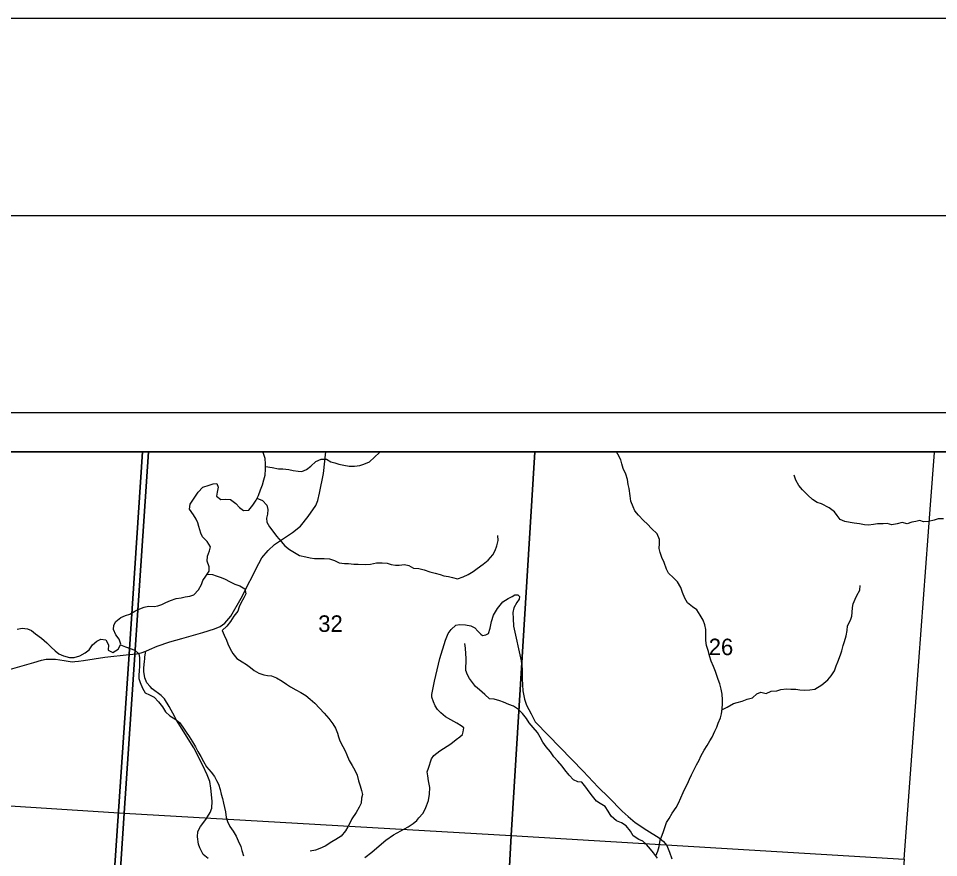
# Model space of a CAD drawing. Extents: x 0 to 34, y 0 to 22.
# Drawn here: x 5.215 to 7.55, y 19.87 to 22 of the extents above; entities that cross this region are included whole.
import ezdxf

# ---------------------------------------------------------------- set-up
doc = ezdxf.new("R2010")
doc.units = 0
for name, color, linetype in [('Default', 7, 'Continuous'), ('GM_X_County_Road', 7, 'Continuous'), ('GM_X_Major_River', 7, 'Continuous'), ('GM_X_Minor_River', 7, 'Continuous'), ('GM_X_Section', 7, 'Continuous'), ('GM_X_Section_Text', 7, 'Continuous'), ('GM_X_State_Route', 7, 'Continuous'), ('GM_X_Township_Road', 7, 'Continuous'), ('SC_Scratch1', 7, 'Continuous'), ('SH_Border', 7, 'Continuous'), ('SH_Cut_Line', 7, 'Continuous'), ('SH_Data', 7, 'Continuous')]:
    doc.layers.add(name, color=color, linetype=linetype)

msp = doc.modelspace()

# ---------------------------------------------------------------- linework, layer by layer
at = {"layer": 'Default'}
for points in [[(5.5445, 20.9), (4.5292, 20.9), (4.4687, 20.0485), (5.483, 19.983)], [(6.5255, 20.9), (5.5445, 20.9), (5.483, 19.983), (6.465, 19.9265)], [(7.5178, 20.9), (6.5255, 20.9), (6.465, 19.9265), (7.462, 19.8663), (7.4997, 20.3683), (7.5295, 20.7659), (7.5396, 20.8985)]]:
    msp.add_lwpolyline(points, close=True, dxfattribs=at)
at = {"layer": 'GM_X_County_Road'}
msp.add_lwpolyline([(5.6967, 19.8686), (5.6838, 19.8781), (5.675, 19.8949), (5.672, 19.9048), (5.6695, 19.9234), (5.6704, 19.9371), (5.6769, 19.9496), (5.6904, 19.9675), (5.7013, 19.9847), (5.7055, 19.9956), (5.7065, 20.0133), (5.7034, 20.0463), (5.7003, 20.0635), (5.6939, 20.0806), (5.6826, 20.1041), (5.66, 20.1491), (5.6159, 20.2195), (5.6119, 20.228), (5.5973, 20.254), (5.5853, 20.2733), (5.5768, 20.2816), (5.5544, 20.2984), (5.5489, 20.3048), (5.541, 20.314), (5.5358, 20.3265), (5.5327, 20.3424), (5.5332, 20.3518), (5.5346, 20.3681), (5.5352, 20.3748), (5.536, 20.3803), (5.5385, 20.3944)], dxfattribs=at)
at = {"layer": 'GM_X_Major_River'}
for points in [[(5.3175, 20.3879), (5.3296, 20.3821), (5.3443, 20.3786), (5.3561, 20.3781), (5.3705, 20.3822), (5.3846, 20.39), (5.3942, 20.3976), (5.403, 20.4104), (5.414, 20.4198), (5.4243, 20.4246), (5.4368, 20.4227), (5.4436, 20.4101), (5.4427, 20.3972), (5.454, 20.391), (5.4678, 20.3993), (5.475, 20.4125), (5.4706, 20.4251), (5.4623, 20.4361), (5.456, 20.4494), (5.4572, 20.4601), (5.4622, 20.4699), (5.4744, 20.48), (5.4869, 20.4849), (5.4979, 20.4886), (5.5105, 20.4957), (5.5231, 20.5017), (5.5341, 20.5062), (5.5451, 20.5083), (5.5591, 20.5079), (5.569, 20.5097), (5.5785, 20.5126), (5.5892, 20.5175), (5.6006, 20.5227), (5.6154, 20.5279), (5.6276, 20.5297), (5.6382, 20.5319), (5.65, 20.5341), (5.6602, 20.5375), (5.6721, 20.5499), (5.679, 20.5631), (5.6828, 20.5733), (5.6905, 20.5847), (5.6989, 20.5975), (5.6986, 20.6081), (5.6934, 20.6226), (5.695, 20.6355), (5.7, 20.6487), (5.702, 20.6593), (5.6941, 20.6726), (5.6821, 20.6841), (5.6776, 20.694), (5.6728, 20.7103), (5.6705, 20.7198), (5.6661, 20.7297), (5.6589, 20.7404), (5.6492, 20.7549), (5.6504, 20.7674), (5.6592, 20.7802), (5.6707, 20.798), (5.6829, 20.8104), (5.6985, 20.8156), (5.7088, 20.8193), (5.7186, 20.8196), (5.722, 20.8101), (5.7188, 20.7976), (5.7176, 20.7878), (5.7286, 20.779), (5.7404, 20.78), (5.7532, 20.7792), (5.7665, 20.7692), (5.7759, 20.7585), (5.7861, 20.7509), (5.7997, 20.7523), (5.8097, 20.7651), (5.8177, 20.7776), (5.8239, 20.7897), (5.8289, 20.8033), (5.8339, 20.8165), (5.8378, 20.8294), (5.8409, 20.8411), (5.8421, 20.8559), (5.8418, 20.8699), (5.8408, 20.8836), (5.8363, 20.8981), (5.8356, 20.9)], [(5.2117, 20.4505), (5.2242, 20.4531), (5.2375, 20.4514), (5.2477, 20.4468), (5.2583, 20.438), (5.2734, 20.4269), (5.2869, 20.4158), (5.2982, 20.4047), (5.3077, 20.3948), (5.3175, 20.3879)]]:
    msp.add_lwpolyline(points, dxfattribs=at)
at = {"layer": 'GM_X_Minor_River'}
for points in [[(5.842, 20.8628), (5.8583, 20.8603), (5.8749, 20.8573), (5.8855, 20.8573), (5.9007, 20.8555), (5.9117, 20.8529), (5.9245, 20.851), (5.9344, 20.8503), (5.9461, 20.8556), (5.9571, 20.8636), (5.9691, 20.8757), (5.9827, 20.8818), (5.9964, 20.8819), (6.0074, 20.8747), (6.018, 20.8724), (6.0282, 20.8691), (6.0403, 20.8664), (6.0543, 20.8638), (6.068, 20.8635), (6.0812, 20.8654), (6.091, 20.8685), (6.1054, 20.8746), (6.1182, 20.8867), (6.1307, 20.8981), (6.132, 20.9)], [(6.8319, 19.8746), (6.8376, 19.8865), (6.8406, 19.899), (6.8432, 19.9146), (6.8485, 19.9271), (6.8519, 19.9366), (6.8552, 19.9472), (6.859, 19.9593), (6.8658, 19.97), (6.874, 19.9836), (6.8842, 19.9973), (6.8895, 20.0083), (6.8955, 20.0224), (6.9019, 20.0356), (6.9068, 20.0463), (6.9124, 20.0573), (6.9173, 20.0698), (6.9226, 20.0808), (6.9286, 20.0922), (6.9354, 20.1059), (6.9418, 20.1176), (6.9466, 20.1275), (6.9553, 20.143), (6.9621, 20.1552), (6.9692, 20.1666), (6.9753, 20.1765), (6.982, 20.1909), (6.9873, 20.2015), (6.9903, 20.2114), (6.9963, 20.2254), (6.9989, 20.2349), (7.0004, 20.2478), (7.0015, 20.2611), (7.0018, 20.2709), (7.0003, 20.2849), (6.9983, 20.2978), (6.9945, 20.3118), (6.9903, 20.3224), (6.9869, 20.3327), (6.9838, 20.3429), (6.9785, 20.355), (6.9724, 20.369), (6.9685, 20.3823), (6.9655, 20.3933), (6.9609, 20.4084), (6.9593, 20.4217), (6.9592, 20.4497), (6.9562, 20.4615), (6.952, 20.4728), (6.9444, 20.4857), (6.936, 20.499), (6.9257, 20.5069), (6.9128, 20.5167), (6.9056, 20.5292), (6.9003, 20.5429), (6.8961, 20.5557), (6.8869, 20.5701), (6.8767, 20.58), (6.8645, 20.5921), (6.8596, 20.6023), (6.8531, 20.6189), (6.8477, 20.6322), (6.8435, 20.6447), (6.8405, 20.6549), (6.8412, 20.6674), (6.8412, 20.6781), (6.8354, 20.6917), (6.8214, 20.7057), (6.8115, 20.717), (6.8013, 20.7257), (6.7887, 20.7394), (6.7788, 20.7507), (6.7747, 20.7605), (6.7689, 20.7753), (6.7674, 20.7886), (6.7643, 20.8075), (6.762, 20.8174), (6.76, 20.8299), (6.7562, 20.8435), (6.7497, 20.8579), (6.7459, 20.8697), (6.7432, 20.8795), (6.736, 20.8943), (6.7326, 20.9)], [(7.2528, 20.7678), (7.2414, 20.7712), (7.2296, 20.7795), (7.2178, 20.7904), (7.2045, 20.8037), (7.195, 20.815), (7.1878, 20.8279), (7.1836, 20.8408)], [(5.8201, 20.7823), (5.8343, 20.7768), (5.8453, 20.7644), (5.848, 20.7537), (5.8473, 20.7416), (5.8447, 20.7317), (5.8455, 20.7219), (5.8519, 20.7098), (5.8607, 20.6992), (5.8698, 20.6859), (5.8812, 20.6723), (5.8907, 20.6617), (5.9025, 20.6523), (5.9154, 20.6447), (5.9279, 20.6375), (5.9445, 20.6334), (5.9548, 20.6312), (5.9658, 20.6297), (5.9782, 20.6297), (5.9907, 20.6294), (6.0044, 20.6283), (6.0165, 20.6241), (6.0286, 20.6188), (6.0419, 20.617), (6.0521, 20.617), (6.0661, 20.6148), (6.0771, 20.6148), (6.0949, 20.6144), (6.1085, 20.6152), (6.1233, 20.6183), (6.1376, 20.6183), (6.1509, 20.6176), (6.1604, 20.6146), (6.1714, 20.6127), (6.1812, 20.6128), (6.1941, 20.6139), (6.2051, 20.6117), (6.2176, 20.6053), (6.2312, 20.6038), (6.2445, 20.6008), (6.2585, 20.5955), (6.2721, 20.5925), (6.2846, 20.5887), (6.2941, 20.5857), (6.3058, 20.5835), (6.3164, 20.5809), (6.3286, 20.5782), (6.3433, 20.5828), (6.3558, 20.5889), (6.369, 20.5965), (6.3792, 20.6038), (6.3943, 20.6152), (6.4071, 20.6251), (6.4185, 20.6391), (6.4249, 20.6497), (6.4286, 20.6619), (6.4323, 20.6752), (6.4316, 20.6877)], [(7.5624, 20.7305), (7.5488, 20.7302), (7.5389, 20.7271), (7.5245, 20.7237), (7.5113, 20.7229), (7.5018, 20.726), (7.4916, 20.7237), (7.4818, 20.7218), (7.4696, 20.7176), (7.4571, 20.721), (7.4443, 20.7176), (7.4314, 20.7149), (7.4189, 20.718), (7.4087, 20.7176), (7.3951, 20.7176), (7.3848, 20.7157), (7.3716, 20.7141), (7.3617, 20.7145), (7.3492, 20.7175), (7.3356, 20.7194), (7.325, 20.7206), (7.3117, 20.7236), (7.2996, 20.7281), (7.292, 20.7384), (7.2852, 20.7482), (7.2719, 20.7577), (7.2528, 20.7678)], [(5.6939, 20.5898), (5.707, 20.5889), (5.7168, 20.5859), (5.7289, 20.581), (5.7392, 20.5768), (5.7502, 20.5712), (5.7638, 20.5647), (5.7767, 20.5602), (5.7892, 20.5523), (5.7919, 20.5394), (5.787, 20.5299), (5.7795, 20.5162), (5.7754, 20.5064), (5.7712, 20.4958), (5.7614, 20.4828), (5.7528, 20.4696), (5.7433, 20.4578), (5.732, 20.4464), (5.7366, 20.4346), (5.7431, 20.4225), (5.7465, 20.4127), (5.7519, 20.4006), (5.7591, 20.3884), (5.769, 20.3756), (5.783, 20.3669), (5.7932, 20.3605), (5.8035, 20.3529), (5.813, 20.3454), (5.8251, 20.3389), (5.8372, 20.3344), (5.8467, 20.3325), (5.8569, 20.3314), (5.8694, 20.3265), (5.8842, 20.3179), (5.8949, 20.3107), (5.9055, 20.3039), (5.9184, 20.2963), (5.9313, 20.2895), (5.9442, 20.282), (5.9555, 20.2729), (5.9673, 20.2623), (5.9909, 20.2366), (6.0026, 20.2234), (6.0129, 20.2097), (6.0194, 20.1988), (6.0243, 20.1863), (6.027, 20.1768), (6.0308, 20.1666), (6.0381, 20.1526), (6.0438, 20.1412), (6.048, 20.131), (6.0545, 20.1173), (6.0613, 20.1041), (6.0689, 20.0927), (6.0746, 20.0795), (6.0781, 20.0655), (6.0823, 20.053), (6.0854, 20.0409), (6.0877, 20.0306), (6.0858, 20.0211), (6.0843, 20.0082), (6.0791, 19.9988), (6.0719, 19.9851), (6.061, 19.9691), (6.0557, 19.9581), (6.0508, 19.9487), (6.0444, 19.938), (6.0339, 19.9247), (6.0199, 19.9167), (6.0097, 19.9103), (5.9935, 19.8996), (5.9798, 19.8935), (5.9685, 19.8897), (5.9553, 19.887)], [(7.2535, 20.309), (7.2683, 20.3216), (7.277, 20.3314), (7.2853, 20.3447), (7.2902, 20.3569), (7.2943, 20.3675), (7.3011, 20.3853), (7.3042, 20.3955), (7.3072, 20.4084), (7.3113, 20.4187), (7.3155, 20.4331), (7.3174, 20.4464), (7.3185, 20.4589), (7.3264, 20.4729), (7.3294, 20.4828), (7.3302, 20.4923), (7.3313, 20.5048), (7.3332, 20.5143), (7.3381, 20.5264), (7.3422, 20.5359), (7.3502, 20.5488), (7.3509, 20.5613)], [(5.4739, 20.4103), (5.4865, 20.4052), (5.4982, 20.4011), (5.5104, 20.3969), (5.5206, 20.3875), (5.5222, 20.378), (5.5222, 20.3685), (5.5218, 20.3572), (5.5215, 20.3435), (5.5208, 20.334), (5.5208, 20.3246), (5.5239, 20.3151), (5.5296, 20.3007), (5.5364, 20.2882), (5.5474, 20.2833), (5.5596, 20.2773), (5.5706, 20.2659), (5.5805, 20.2534), (5.5877, 20.2402), (5.5991, 20.2303), (5.6116, 20.2224), (5.6234, 20.2133), (5.6317, 20.2016), (5.6405, 20.1891), (5.6485, 20.1774), (5.6565, 20.1641), (5.6645, 20.1517), (5.6705, 20.1399), (5.6774, 20.1267), (5.6843, 20.1142), (5.6923, 20.1005), (5.704, 20.0869), (5.712, 20.0763), (5.7173, 20.0665), (5.7223, 20.0566), (5.7269, 20.0434), (5.7292, 20.0316), (5.7323, 20.0207), (5.7349, 20.0085), (5.7376, 19.9972), (5.7399, 19.9862), (5.7419, 19.9722), (5.7453, 19.9619), (5.751, 19.9491), (5.7598, 19.9373), (5.7674, 19.9252), (5.7723, 19.9127), (5.7788, 19.8987), (5.7819, 19.8889), (5.7857, 19.8748)], [(6.3504, 20.3872), (6.3496, 20.402), (6.3476, 20.4134)], [(6.8362, 19.8687), (6.8263, 19.8823), (6.8191, 19.8922), (6.8088, 19.9039), (6.7993, 19.9122), (6.7891, 19.9163), (6.7747, 19.9258), (6.7678, 19.9379), (6.7572, 19.9511), (6.745, 19.9591), (6.7325, 19.9636), (6.7193, 19.9753), (6.7109, 19.9882), (6.7033, 20.0003), (6.6908, 20.0078), (6.6813, 20.0139), (6.6714, 20.0267), (6.663, 20.0377), (6.655, 20.0494), (6.6444, 20.0615), (6.6346, 20.063), (6.6236, 20.0676), (6.6125, 20.08), (6.6015, 20.0929), (6.5947, 20.1027), (6.5833, 20.1156), (6.5738, 20.1258), (6.565, 20.1387), (6.5544, 20.1515), (6.5453, 20.1633), (6.5388, 20.1765), (6.5316, 20.1883), (6.5206, 20.2004), (6.5107, 20.2125), (6.5042, 20.2238), (6.4943, 20.2363), (6.4841, 20.2465), (6.4708, 20.2545), (6.459, 20.2594), (6.4458, 20.265), (6.4363, 20.2684), (6.4219, 20.2722), (6.4098, 20.2736), (6.398, 20.2842), (6.3844, 20.2963), (6.3745, 20.305), (6.3673, 20.3149), (6.3593, 20.3247), (6.3547, 20.3345), (6.3505, 20.3451), (6.3501, 20.355), (6.3512, 20.3649), (6.3512, 20.3762), (6.3504, 20.3872)], [(7.0001, 20.2455), (7.0136, 20.252), (7.0291, 20.2615), (7.039, 20.2638), (7.0514, 20.2672), (7.0639, 20.2722), (7.0775, 20.276), (7.0889, 20.2859), (7.0991, 20.2905), (7.1123, 20.2871), (7.1252, 20.2924), (7.1395, 20.294), (7.1498, 20.2974), (7.1638, 20.2986), (7.1751, 20.2979), (7.1876, 20.2975), (7.1975, 20.2964), (7.2103, 20.2953), (7.2228, 20.2961), (7.2357, 20.2976), (7.2535, 20.309)]]:
    msp.add_lwpolyline(points, dxfattribs=at)
at = {"layer": 'GM_X_Section'}
for points in [[(4.4687, 20.0485), (5.483, 19.983), (5.4174, 18.9797), (4.4009, 19.0464)], [(6.465, 19.9265), (6.4104, 18.9115), (5.4174, 18.9797), (5.483, 19.983)], [(6.465, 19.9265), (7.462, 19.8663), (7.3808, 18.8429), (6.4104, 18.9115)]]:
    msp.add_lwpolyline(points, close=True, dxfattribs=at)
at = {"layer": 'GM_X_State_Route'}
for points in [[(5.5385, 20.3944), (5.5477, 20.3987), (5.5673, 20.407), (5.5991, 20.418), (5.6294, 20.4265), (5.6358, 20.4284), (5.6829, 20.4421), (5.7123, 20.451), (5.7266, 20.4572), (5.7389, 20.4654), (5.7542, 20.4828), (5.7798, 20.5285), (5.8251, 20.6165), (5.8328, 20.6312), (5.8487, 20.6498), (5.8643, 20.6648), (5.8878, 20.6804), (5.9102, 20.6957), (5.9307, 20.7119), (5.9499, 20.7358), (5.9696, 20.7638), (5.9743, 20.777), (5.979, 20.7956), (5.9888, 20.845), (5.9953, 20.9)], [(5.0528, 20.3185), (5.0705, 20.3213), (5.1135, 20.3295), (5.1825, 20.3456), (5.2536, 20.3659), (5.2734, 20.3716), (5.2856, 20.3737), (5.2946, 20.3742), (5.2999, 20.3742), (5.3091, 20.3739), (5.3309, 20.3703), (5.3413, 20.3689), (5.3509, 20.3675), (5.3578, 20.368), (5.3675, 20.3689), (5.3802, 20.3703), (5.4071, 20.3751), (5.4344, 20.379), (5.4957, 20.3859), (5.5145, 20.3877), (5.526, 20.39), (5.5385, 20.3944)]]:
    msp.add_lwpolyline(points, dxfattribs=at)
at = {"layer": 'GM_X_Township_Road'}
msp.add_lwpolyline([(6.094, 19.8705), (6.1114, 19.8845), (6.1301, 19.9007), (6.1472, 19.9145), (6.1665, 19.928), (6.2038, 19.9488), (6.2164, 19.9567), (6.2255, 19.965), (6.2313, 19.9714), (6.2407, 19.9825), (6.2473, 19.993), (6.2505, 20.0015), (6.2558, 20.0151), (6.2577, 20.0317), (6.2586, 20.0482), (6.2555, 20.0653), (6.2537, 20.0778), (6.2519, 20.0878), (6.2552, 20.0974), (6.2632, 20.1207), (6.269, 20.1292), (6.2843, 20.1412), (6.3124, 20.1595), (6.3259, 20.1705), (6.3347, 20.1766), (6.3413, 20.1831), (6.3433, 20.1895), (6.3454, 20.1996), (6.3387, 20.2051), (6.3271, 20.2115), (6.3124, 20.2201), (6.2989, 20.228), (6.2864, 20.2378), (6.2785, 20.2461), (6.2726, 20.2559), (6.2681, 20.2654), (6.2638, 20.2773), (6.2635, 20.284), (6.2708, 20.3183), (6.284, 20.3761), (6.2983, 20.4223), (6.3057, 20.4388), (6.3133, 20.4494), (6.3246, 20.4599), (6.3344, 20.462), (6.3494, 20.4611), (6.3626, 20.4587), (6.3727, 20.4535), (6.3809, 20.4452), (6.388, 20.4373), (6.3928, 20.4345), (6.4008, 20.4354), (6.4075, 20.4388), (6.4118, 20.4525), (6.4152, 20.4697), (6.4204, 20.4853), (6.4305, 20.503), (6.4444, 20.5197), (6.4577, 20.5281), (6.4675, 20.5333), (6.4742, 20.537), (6.4822, 20.537), (6.4861, 20.5327), (6.4858, 20.5266), (6.4797, 20.518), (6.4719, 20.5039), (6.469, 20.4923), (6.4699, 20.4773), (6.4715, 20.4577), (6.4904, 20.37), (6.4929, 20.3489), (6.4935, 20.3238), (6.495, 20.2935), (6.499, 20.2721), (6.5045, 20.2577), (6.5158, 20.2351), (6.5263, 20.2147), (6.56, 20.1802), (6.648, 20.0901), (6.6856, 20.0491), (6.7131, 20.0228), (6.7471, 19.9879), (6.7624, 19.9745), (6.7798, 19.9595), (6.8091, 19.9402), (6.8403, 19.9206), (6.852, 19.9115), (6.8605, 19.9014), (6.8673, 19.8842), (6.8728, 19.8674)], dxfattribs=at)
at = {"layer": 'SC_Scratch1'}
for points in [[(5.53, 20.9), (2.1, 20.9), (2.1, 19.1982), (2.3572, 19.1804), (3.3448, 19.1146), (4.3628, 19.0495), (4.7394, 19.0241), (4.7997, 19.0196), (5.182, 18.9932), (5.4007, 18.9779), (5.4089, 19.0989), (5.4469, 19.6641), (5.4955, 20.3864)], [(8.9, 18.7389), (8.9, 20.9), (5.53, 20.9), (5.4955, 20.3864), (5.4469, 19.6641), (5.4089, 19.0989), (5.4007, 18.9779), (5.4885, 18.9719), (5.9889, 18.9377), (6.8273, 18.8804), (7.2159, 18.8539), (8.2061, 18.7863)]]:
    msp.add_lwpolyline(points, close=True, dxfattribs=at)
at = {"layer": 'SH_Border'}
msp.add_lwpolyline([(1.5, 21.5), (33.5, 21.5), (33.5, 0.5), (1.5, 0.5)], close=True, dxfattribs=at)
at = {"layer": 'SH_Cut_Line'}
msp.add_lwpolyline([(0, 0), (34, 0), (34, 22), (0, 22)], close=True, dxfattribs=at)
at = {"layer": 'SH_Data'}
for p, q in [((2, 21), (9, 21)), ((2.1, 20.9), (8.9, 20.9))]:
    msp.add_line(p, q, dxfattribs=at)

# ---------------------------------------------------------------- texts
at = {"layer": 'GM_X_Section_Text'}
for s, p in [('32', (5.9756, 20.4433)), ('26', (6.9664, 20.3842))]:
    msp.add_text(s, height=0.04186, rotation=0, dxfattribs=at).set_placement(p)

doc.saveas('drawing.dxf')
